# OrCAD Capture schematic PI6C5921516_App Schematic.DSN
size B; title: PI6C5921516 Application Circuit; rev: 1.0; note: Diodes Inc. Clock IC Application Engineering
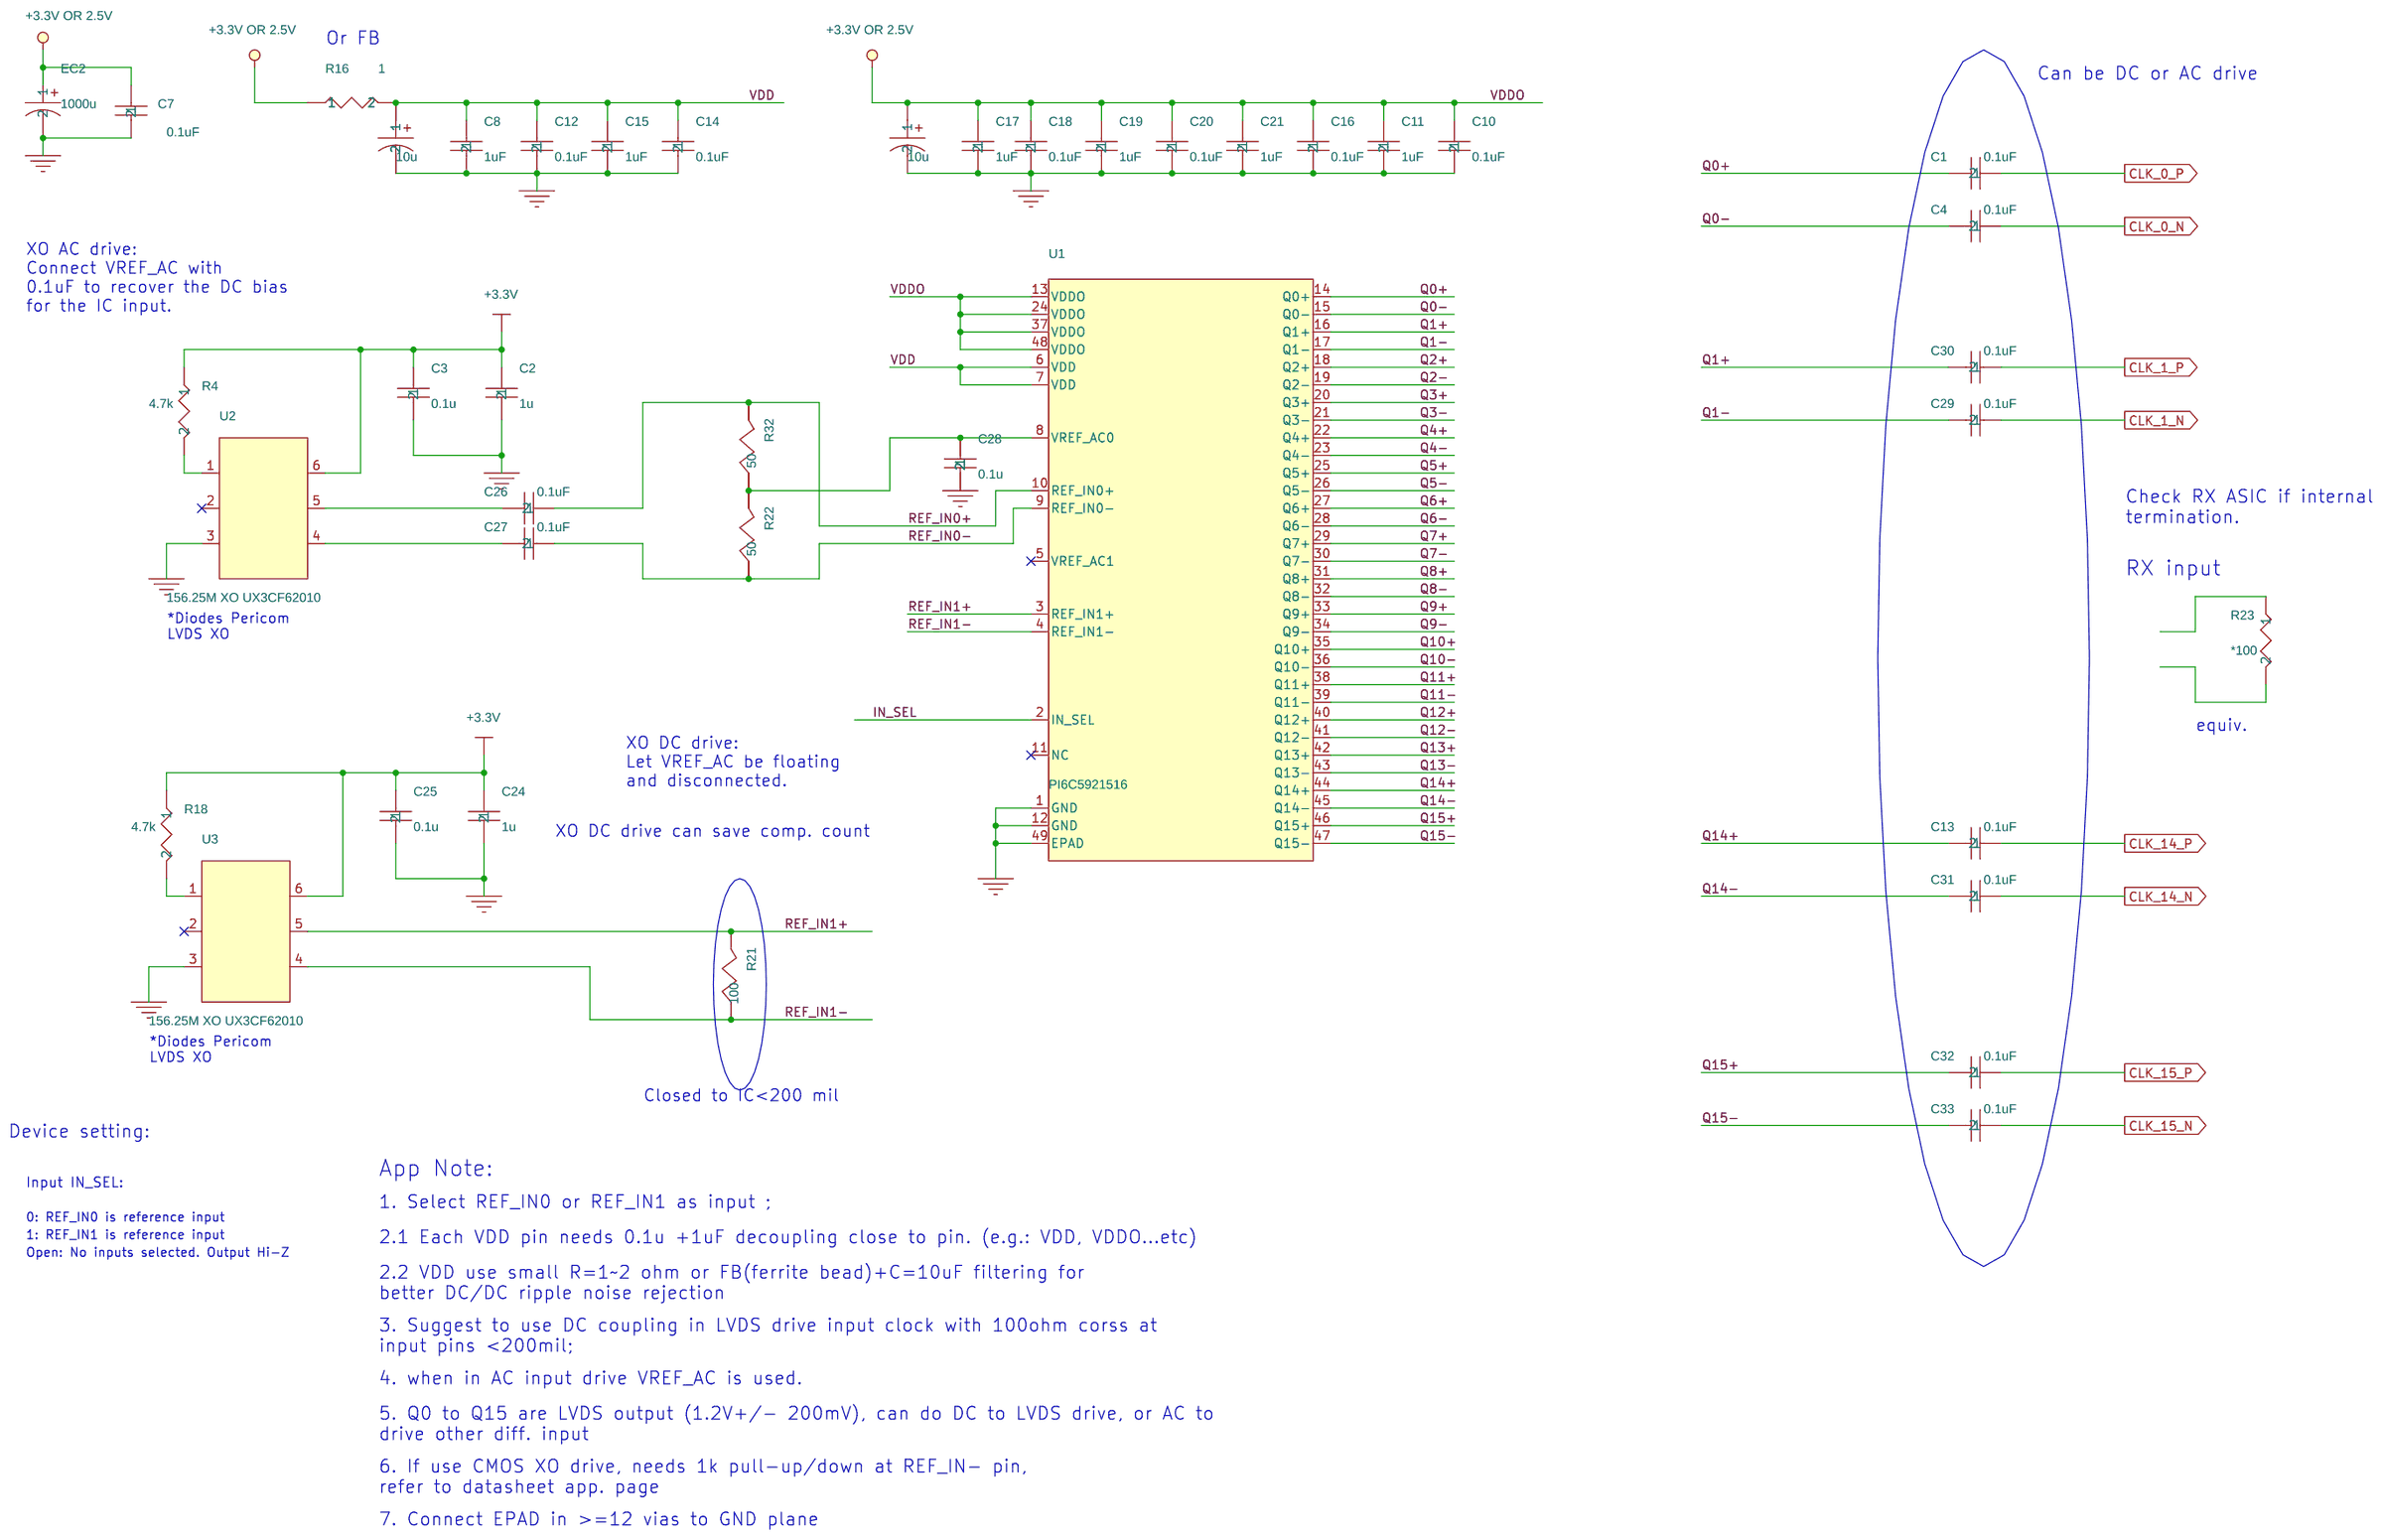
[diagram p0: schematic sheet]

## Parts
C1  0.1uF  [CC_0402]
C2  1u  [CC_0402]
C3  0.1u  [CC_0402]
C4  0.1uF  [CC_0402]
C7  0.1uF  [CC_0402]
C8  1uF  [CC_0402]
C10  0.1uF  [CC_0402]
C11  1uF  [CC_0402]
C12  0.1uF  [CC_0402]
C13  0.1uF  [CC_0402]
C14  0.1uF  [CC_0402]
C15  1uF  [CC_0402]
C16  0.1uF  [CC_0402]
C17  1uF  [CC_0402]
C18  0.1uF  [CC_0402]
C19  1uF  [CC_0402]
C20  0.1uF  [CC_0402]
C21  1uF  [CC_0402]
C24  1u  [CC_0402]
C25  0.1u  [CC_0402]
C26  0.1uF  [CC_0402]
C27  0.1uF  [CC_0402]
C28  0.1u  [CC_0402]
C29  0.1uF  [CC_0402]
C30  0.1uF  [CC_0402]
C31  0.1uF  [CC_0402]
C32  0.1uF  [CC_0402]
C33  0.1uF  [CC_0402]
EC1  10u  [CAP1000UF]
EC2  1000u  [CAP1000UF]
EC3  10u  [CAP1000UF]
R4  4.7k  [R_0402]
R16  1  [R_0402]
R18  4.7k  [R_0402]
R21  100
R22  50
R23  *100  [R_0402]
R32  50
U1  PI6C5921516  [TQFN48]
U2  156.25M XO UX3CF62010  [XO 5X7]
U3  156.25M XO UX3CF62010  [XO 5X7]

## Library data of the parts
C1 = C_10n_0402_16
C2 = C_0.1u_0402_1
C3 = C_0.1u_0402_4
C4 = C_10n_0402_7
C7 = C_10n_0402_18
C8 = C_10n_0402_10
C10 = C_10n_0402_15
C11 = C_10n_0402_2
C12 = C_10n_0402_21
C13 = C_10n_0402_12
C14 = C_10n_0402_17
C15 = C_10n_0402_14
C16 = C_10n_0402_19
C17 = C_10n_0402_4
C18 = C_10n_0402_1
C19 = C_10n_0402_9
C20 = C_10n_0402_13
C21 = C_10n_0402_20
C24 = C_0.1u_0402_3
C25 = C_0.1u_0402_2
C26 = C_10n_0402_6
C27 = C_10n_0402_3
C28 = C_0.1u_0402
C29 = C_10n_0402
C30 = C_10n_0402_5
C31 = C_10n_0402_22
C32 = C_10n_0402_11
C33 = C_10n_0402_8
EC1 = C_alum_1000u
EC2 = C_alum_1000u_2
EC3 = C_alum_1000u_1
R4 = R_0402_1
R16 = R_0402
R18 = R_0402_2
R21 R22 R32 = res1
R23 = R_0
U1 = PI6C49S1510ZDE@TQFN48_6
U2 U3 = XO_5X7

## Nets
+3.3V: C2.1 C3.1 C24.1 C25.1 R4.1 R18.1 U2.6 U3.6
+3.3V or 2.5V: C7.1 C10.1 C11.1 C16.1 C17.1 C18.1 C19.1 C20.1 C21.1 EC1.1 EC2.1 R16.1 U1.13(VDDO) U1.24(VDDO) U1.37(VDDO) U1.48(VDDO)
GND: C2.2 C3.2 C7.2 C8.2 C10.2 C11.2 C12.2 C14.2 C15.2 C16.2 C17.2 C18.2 C19.2 C20.2 C21.2 C24.2 C25.2 C28.2 EC1.2 EC2.2 EC3.2 U1.1(GND) U1.12(GND) U1.49(EPAD) U2.3 U3.3
VDD: C8.1 C12.1 C14.1 C15.1 EC3.1 R16.2 U1.6(VDD) U1.7(VDD)
CLK_0_N: C4.1
CLK_0_P: C1.1
CLK_1_N: C29.1
CLK_1_P: C30.1
CLK_14_N: C31.1
CLK_14_P: C13.1
CLK_15_N: C33.1
CLK_15_P: C32.1
IN_SEL: U1.2(IN_SEL)
Q0+: C1.2 U1.14(Q0+)
Q0-: C4.2 U1.15(Q0-)
Q1+: C30.2 U1.16(Q1+)
Q1-: C29.2 U1.17(Q1-)
Q2+: U1.18(Q2+)
Q2-: U1.19(Q2-)
Q3+: U1.20(Q3+)
Q3-: U1.21(Q3-)
Q4+: U1.22(Q4+)
Q4-: U1.23(Q4-)
Q5+: U1.25(Q5+)
Q5-: U1.26(Q5-)
Q6+: U1.27(Q6+)
Q6-: U1.28(Q6-)
Q7+: U1.29(Q7+)
Q7-: U1.30(Q7-)
Q8+: U1.31(Q8+)
Q8-: U1.32(Q8-)
Q9+: U1.33(Q9+)
Q9-: U1.34(Q9-)
Q10+: U1.35(Q10+)
Q10-: U1.36(Q10-)
Q11+: U1.38(Q11+)
Q11-: U1.39(Q11-)
Q12+: U1.40(Q12+)
Q12-: U1.41(Q12-)
Q13+: U1.42(Q13+)
Q13-: U1.43(Q13-)
Q14+: C13.2 U1.44(Q14+)
Q14-: C31.2 U1.45(Q14-)
Q15+: C32.2 U1.46(Q15+)
Q15-: C33.2 U1.47(Q15-)
REF_IN0+: C26.1 R32.2 U1.10(REF_IN0+)
REF_IN0-: C27.1 R22.1 U1.9(REF_IN0-)
REF_IN1+: R21.2 U1.3(REF_IN1+) U3.5
REF_IN1-: R21.1 U1.4(REF_IN1-) U3.4
N4637081: R18.2 U3.1
N4646518: C28.1 R22.2 R32.1 U1.8(VREF_AC0)
N4646634: R4.2 U2.1
N4646726: C26.2 U2.5
N4646730: C27.2 U2.4

Not connected (* = marked no-connect by the designer): R23 1 2; U1 5(VREF_AC1)* 11(NC)*; U2 2*; U3 2*

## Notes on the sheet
- Or FB
- Can be DC or AC drive
- XO AC drive:
  Connect VREF_AC with
  0.1uF to recover the DC bias
  for the IC input.
- Check RX ASIC if internal
  termination.
- RX input
- *Diodes Pericom
  LVDS XO
- equiv.
- XO DC drive:
  Let VREF_AC be floating
  and disconnected.
- XO DC drive can save comp. count
- *Diodes Pericom
  LVDS XO
- Closed to IC<200 mil
- Device setting:
- App Note:
- Input IN_SEL:
- 1. Select REF_IN0 or REF_IN1 as input ;
- 0: REF_IN0 is reference input
- 1: REF_IN1 is reference input
- Open: No inputs selected. Output Hi-Z
- 2.1 Each VDD pin needs 0.1u +1uF decoupling close to pin. (e.g.: VDD, VDDO...etc)
- 2.2 VDD use small R=1~2 ohm or FB(ferrite bead)+C=10uF filtering for
  better DC/DC ripple noise rejection
- 3. Suggest to use DC coupling in LVDS drive input clock with 100ohm corss at
  input pins <200mil;
- 4. when in AC input drive VREF_AC is used.
- 5. Q0 to Q15 are LVDS output (1.2V+/- 200mV), can do DC to LVDS drive, or AC to
  drive other diff. input
- 6. If use CMOS XO drive, needs 1k pull-up/down at REF_IN- pin,
  refer to datasheet app. page
- 7. Connect EPAD in >=12 vias to GND plane
